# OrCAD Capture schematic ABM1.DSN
size A
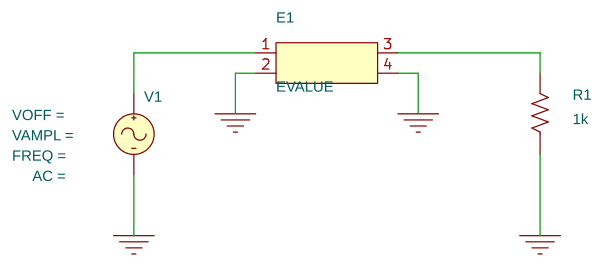
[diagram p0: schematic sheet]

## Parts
E1  EVALUE
R1  1k  [AX/RC05]
V1  VSIN

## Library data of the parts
E1 = EVALUE
R1 = R
V1 = VSIN

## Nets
0: E1.2(IN-) E1.4(OUT-) R1.1 V1.2(-)
N00106: E1.1(IN+) V1.1(+)
N00113: E1.3(OUT+) R1.2
